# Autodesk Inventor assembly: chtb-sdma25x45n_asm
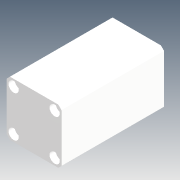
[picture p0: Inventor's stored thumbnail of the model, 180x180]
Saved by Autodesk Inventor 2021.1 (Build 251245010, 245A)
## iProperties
Company: Microsoft
Created: 2018-05
Part Number: chtb-sdma25x45n_asm
Description: STEP AP214
Document SubType Name: Assembly
Designer: user
Title: chtb-sdma25x45n_asm.STEP
Author: Windows
Revision Number: ÈÎºÎ
Sending System: SolidWorks 2015
Preprocessor: SwSTEP 2.0
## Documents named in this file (4)
- D:\Vault_2016\Projekty\Clamptek\Hydraulic\CHTB\CHTB-25\Inventor\chtb-sdma25x45n\chtb-sdma25x45n_asm.iam
- D:\Vault_2016\Projekty\Clamptek\Hydraulic\CHTB\CHTB-25\Inventor\chtb-sdma25x45n\CHTB-25QG.ipt
- D:\Vault_2016\Projekty\Clamptek\Hydraulic\CHTB\CHTB-25\Inventor\chtb-sdma25x45n\CHTB-SDMA25X45NBT.ipt
- D:\Vault_2016\Projekty\Clamptek\Hydraulic\CHTB\CHTB-25\Inventor\chtb-sdma25x45n\CHTB-SDMA25X45NHSG.ipt
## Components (3 placed, 3 different names)
1. CHTB-25QG_1
2. CHTB-SDMA25X45NBT_2
3. CHTB-SDMA25X45NHSG_3
